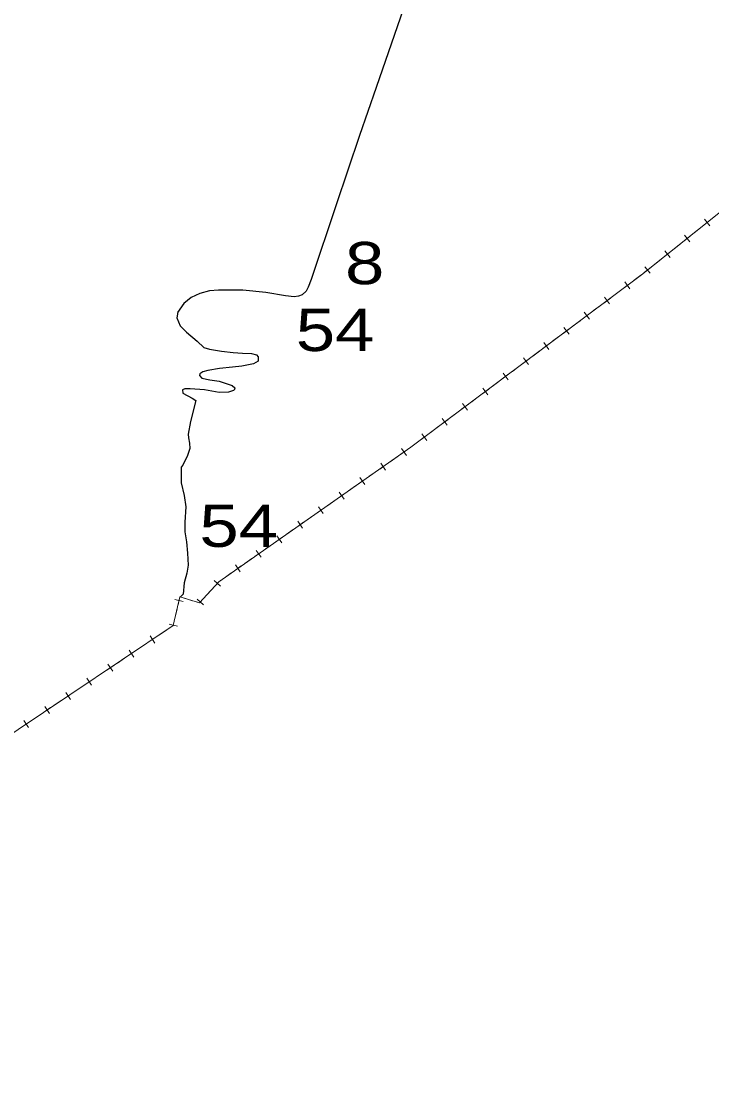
# Model space of a CAD drawing. Extents: x 476989 to 498418, y 4381813 to 4416555.
# Drawn here: x 486843 to 487660, y 4382283 to 4383532 of the extents above; entities that cross this region are included whole.
import ezdxf

# ---------------------------------------------------------------- set-up
doc = ezdxf.new("R2010")
doc.units = 0
doc.header["$LTSCALE"] = 20
for name, color, linetype, lineweight in [('13', 7, 'Continuous', 13), ('34', 7, 'Continuous', 13), ('6', 7, 'Continuous', 25)]:
    doc.layers.add(name, color=color, linetype=linetype, lineweight=lineweight)

msp = doc.modelspace()

# ---------------------------------------------------------------- linework, layer by layer
at = {"layer": '34'}
for p, q in [((487657.75, 4383289.96), (487651.52, 4383297.78)), ((487646.82, 4383287.64), (487639, 4383281.41)), ((487658.55, 4383296.99), (487650.73, 4383290.76)), ((487635.09, 4383278.3), (487627.27, 4383272.07)), ((487634.3, 4383271.27), (487628.07, 4383279.09)), ((487610.85, 4383252.58), (487604.61, 4383260.4)), ((487623.36, 4383268.95), (487615.54, 4383262.72)), ((487599.91, 4383250.26), (487592.09, 4383244.03)), ((487611.64, 4383259.61), (487603.82, 4383253.37)), ((487588.19, 4383240.92), (487580.37, 4383234.68)), ((487587.39, 4383233.89), (487581.16, 4383241.71)), ((487564.44, 4383222.61), (487556.43, 4383216.63)), ((487563.42, 4383215.61), (487557.44, 4383223.62)), ((487576.44, 4383231.58), (487568.43, 4383225.6)), ((487552.42, 4383213.63), (487544.41, 4383207.65)), ((487540.41, 4383204.66), (487532.4, 4383198.67)), ((487539.4, 4383197.66), (487533.41, 4383205.67)), ((487516.39, 4383186.71), (487508.38, 4383180.72)), ((487515.38, 4383179.71), (487509.39, 4383187.72)), ((487528.4, 4383195.68), (487520.39, 4383189.69)), ((487504.37, 4383177.73), (487496.36, 4383171.74)), ((487492.36, 4383168.76), (487484.35, 4383162.77)), ((487491.35, 4383161.76), (487485.37, 4383169.77)), ((487468.34, 4383150.8), (487460.33, 4383144.82)), ((487467.33, 4383143.81), (487461.34, 4383151.82)), ((487480.35, 4383159.78), (487472.34, 4383153.79)), ((487456.33, 4383141.83), (487448.31, 4383135.84)), ((487432.3, 4383123.87), (487424.29, 4383117.89)), ((487444.32, 4383132.85), (487436.31, 4383126.87)), ((487443.31, 4383125.85), (487437.32, 4383133.87)), ((487420.29, 4383114.9), (487412.28, 4383108.92)), ((487419.28, 4383107.9), (487413.3, 4383115.91)), ((487395.26, 4383089.95), (487389.27, 4383097.96)), ((487408.28, 4383105.92), (487400.27, 4383099.94)), ((487384.25, 4383087.97), (487376.24, 4383081.98)), ((487396.27, 4383096.95), (487388.26, 4383090.96)), ((487372.25, 4383079), (487364.24, 4383073.01)), ((487371.23, 4383072), (487365.25, 4383080.01)), ((487348.22, 4383061.05), (487340.21, 4383055.06)), ((487347.21, 4383054.05), (487341.22, 4383062.06)), ((487360.23, 4383070.02), (487352.22, 4383064.03)), ((487336.21, 4383052.07), (487328.2, 4383046.08)), ((487324.2, 4383043.09), (487316.19, 4383037.11)), ((487323.19, 4383036.1), (487317.2, 4383044.11)), ((487300.09, 4383025.26), (487291.9, 4383019.52)), ((487298.86, 4383018.3), (487293.13, 4383026.49)), ((487312.18, 4383034.12), (487304.17, 4383028.13)), ((487287.8, 4383016.66), (487279.61, 4383010.92)), ((487263.24, 4382999.45), (487255.05, 4382993.71)), ((487275.53, 4383008.06), (487267.34, 4383002.32)), ((487274.3, 4383001.09), (487268.56, 4383009.28)), ((487250.96, 4382990.85), (487242.77, 4382985.11)), ((487249.74, 4382983.89), (487244, 4382992.08)), ((487226.4, 4382973.64), (487218.21, 4382967.91)), ((487225.17, 4382966.68), (487219.43, 4382974.87)), ((487238.68, 4382982.24), (487230.49, 4382976.51)), ((487214.11, 4382965.04), (487205.92, 4382959.3)), ((487189.55, 4382947.83), (487181.36, 4382942.1)), ((487201.84, 4382956.44), (487193.64, 4382950.7)), ((487200.61, 4382949.48), (487194.87, 4382957.67)), ((487177.27, 4382939.23), (487169.08, 4382933.5)), ((487176.04, 4382932.27), (487170.31, 4382940.46)), ((487151.48, 4382915.06), (487145.74, 4382923.26)), ((487164.99, 4382930.63), (487156.79, 4382924.89)), ((487140.42, 4382913.42), (487132.23, 4382907.69)), ((487152.71, 4382922.03), (487144.52, 4382916.29)), ((487128.14, 4382904.82), (487119.95, 4382899.09)), ((487126.92, 4382897.86), (487121.18, 4382906.05)), ((487103.58, 4382887.62), (487095.39, 4382881.88)), ((487102.35, 4382880.65), (487096.62, 4382888.84)), ((487115.86, 4382896.22), (487107.67, 4382890.48)), ((487091.29, 4382879.01), (487083.1, 4382873.28)), ((487078.96, 4382863.75), (487071.6, 4382870.52)), ((487034.84, 4382845.47), (487025.1, 4382847.76)), ((487045.81, 4382846.49), (487036.25, 4382849.4)), ((487058.66, 4382841.68), (487051.3, 4382848.45)), ((487068.51, 4382859.77), (487061.74, 4382852.41)), ((487027.68, 4382836.88), (487025.39, 4382827.15)), ((487015.05, 4382811.68), (487006.74, 4382806.12)), ((487027.97, 4382816.28), (487018.23, 4382818.57)), ((487002.59, 4382803.34), (486994.28, 4382797.78)), ((487001.22, 4382796.4), (486995.66, 4382804.71)), ((486977.67, 4382786.66), (486969.36, 4382781.09)), ((486976.3, 4382779.72), (486970.73, 4382788.03)), ((486990.13, 4382795), (486981.82, 4382789.43)), ((486965.21, 4382778.31), (486956.9, 4382772.75)), ((486940.28, 4382761.63), (486931.97, 4382756.07)), ((486952.75, 4382769.97), (486944.44, 4382764.41)), ((486951.38, 4382763.04), (486945.81, 4382771.35)), ((486927.83, 4382753.29), (486919.52, 4382747.73)), ((486926.45, 4382746.36), (486920.89, 4382754.67)), ((486902.91, 4382736.61), (486894.6, 4382731.05)), ((486901.53, 4382729.67), (486895.97, 4382737.98)), ((486915.36, 4382744.95), (486907.05, 4382739.39)), ((486890.44, 4382728.27), (486882.13, 4382722.7)), ((486865.52, 4382711.58), (486857.21, 4382706.02)), ((486877.98, 4382719.93), (486869.67, 4382714.37)), ((486876.61, 4382712.99), (486871.05, 4382721.3)), ((486853.06, 4382703.25), (486844.75, 4382697.68)), ((486851.69, 4382696.31), (486846.13, 4382704.62))]:
    msp.add_line(p, q, dxfattribs=at)
for points in [[(487676.62, 4383311.4), (487577, 4383232), (487304, 4383028), (487077, 4382869), (487054, 4382844), (487031, 4382851), (487023, 4382817), (486778, 4382653), (486740, 4382634), (486629, 4382532), (486583, 4382537), (486557, 4382471), (486289, 4382313), (486283, 4382292), (486265, 4382283)], [(487079.02, 4382870.41), (487077, 4382869), (487071.9, 4382863.45)], [(487031.47, 4382850.86), (487031, 4382851), (487028.82, 4382841.75)], [(487058.36, 4382848.74), (487054, 4382844), (487050.6, 4382845.04)], [(487024.24, 4382822.29), (487023, 4382817), (487019.2, 4382814.46)]]:
    msp.add_lwpolyline(points, dxfattribs=at)
at = {"layer": '6'}
for points in [[(487298.99, 4383557.78), (487262.98, 4383453.83), (487243.49, 4383397.09), (487215.9, 4383314.87), (487186.11, 4383226.43), (487182.63, 4383217.34), (487180.29, 4383212.75), (487175.73, 4383208.4), (487171.21, 4383207.02), (487166.04, 4383206.21), (487156.02, 4383207.28), (487132.44, 4383211.07), (487105.23, 4383213.77), (487076.64, 4383213.95), (487066.01, 4383213.3), (487054.41, 4383209.96), (487044.4, 4383205.38), (487035.65, 4383198.23), (487028.06, 4383187.44)], [(487028.33, 4383187.82), (487027.14, 4383181.15), (487031.16, 4383171.92), (487038.79, 4383164.3), (487051.24, 4383153.47), (487059.28, 4383146.25), (487066.11, 4383144.25), (487080.17, 4383141.84), (487093.82, 4383140.24), (487105.07, 4383139.44), (487115.52, 4383139.04), (487121.54, 4383137.43), (487123.55, 4383135.02), (487123.55, 4383129.96), (487117.93, 4383126.75), (487104.27, 4383123.94), (487093.02, 4383122.74), (487077.76, 4383121.13), (487064.1, 4383118.72), (487058.07, 4383117.12), (487054.46, 4383115.11), (487054.05, 4383113.1), (487056.87, 4383109.89), (487066.51, 4383107.88), (487077.35, 4383106.28), (487087, 4383103.07), (487092.62, 4383101.06), (487095.83, 4383098.25), (487095.43, 4383096.24), (487094.23, 4383095.04), (487088.6, 4383093.43), (487077.35, 4383093.03), (487060.08, 4383095.84), (487043.21, 4383097.05), (487036.78, 4383097.05), (487033.97, 4383095.84), (487034.37, 4383092.23), (487045.62, 4383086.21), (487049.64, 4383083.4), (487043.61, 4383058.64), (487040.8, 4383043.38), (487041.2, 4383039.37), (487042.4, 4383032.95), (487042.85, 4383026.65), (487040.03, 4383018.22), (487034.41, 4383006.98), (487032.4, 4383004.57), (487032.4, 4382998.15), (487032.4, 4382986.11), (487036.02, 4382971.02), (487038.03, 4382957.37), (487036.82, 4382939.39), (487036.82, 4382928.15), (487038.83, 4382916.11), (487040.03, 4382902.87), (487040.84, 4382888.42), (487039.23, 4382879.18), (487036.02, 4382867.67), (487034.81, 4382854.02), (487032, 4382851.61)]]:
    msp.add_lwpolyline(points, dxfattribs=at)

# ---------------------------------------------------------------- texts
at = {"layer": '13', "width": 1.25}
for s, p in [('8', (487226.3, 4383221.02)), ('54', (487168.07, 4383141.9)), ('54', (487054.02, 4382910.13))]:
    msp.add_text(s, height=50, dxfattribs=at).set_placement(p)

doc.saveas('drawing.dxf')
